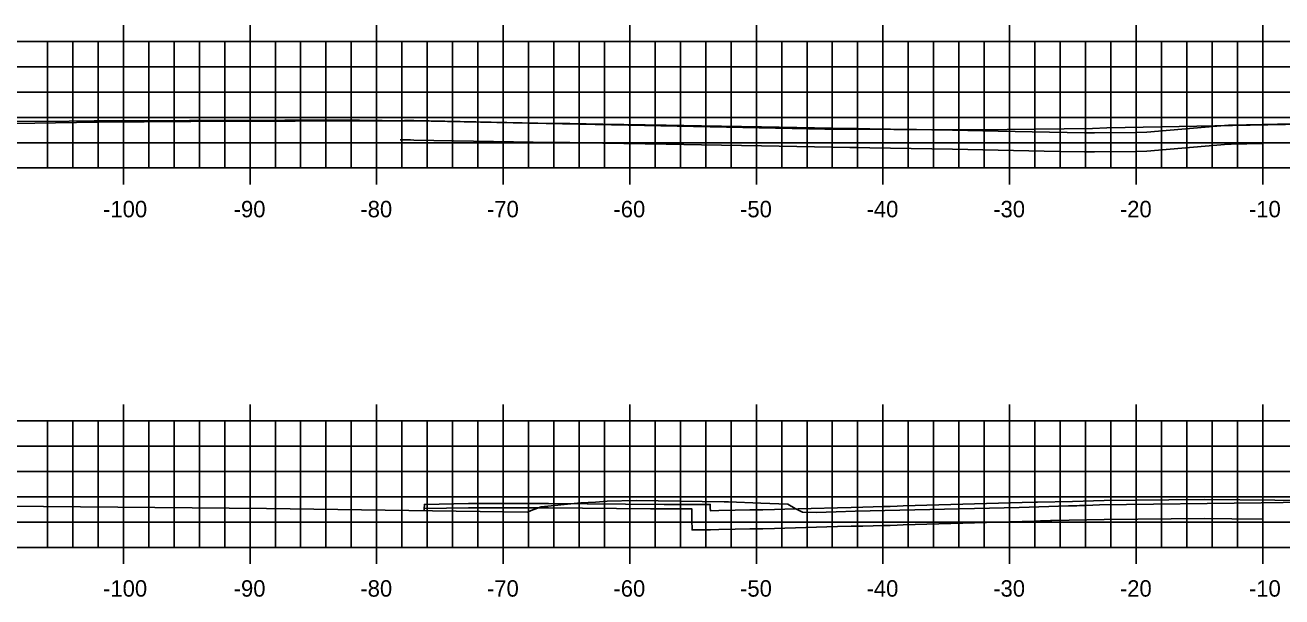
# Model space of a CAD drawing. Extents: x 40011 to 50684, y 49949 to 72236.
# Drawn here: x 41645.7 to 41745, y 68462.9 to 68508.1 of the extents above; entities that cross this region are included whole.
import ezdxf

# ---------------------------------------------------------------- set-up
doc = ezdxf.new("R2010")
doc.units = 0
for name, color, linetype in [('51', 7, 'Continuous'), ('53', 7, 'Continuous'), ('55', 7, 'Continuous'), ('57', 7, 'Continuous'), ('58', 7, 'Continuous'), ('59', 7, 'Continuous'), ('60', 7, 'Continuous')]:
    doc.layers.add(name, color=color, linetype=linetype)

msp = doc.modelspace()

# ---------------------------------------------------------------- linework, layer by layer
at = {"layer": '51'}
for p, q in [((41647.504, 68496.804), (41647.504, 68506.804)), ((41649.504, 68496.804), (41649.504, 68506.804)), ((41651.504, 68496.804), (41651.504, 68506.804)), ((41655.504, 68496.804), (41655.504, 68506.804)), ((41657.504, 68496.804), (41657.504, 68506.804)), ((41659.504, 68496.804), (41659.504, 68506.804)), ((41661.504, 68496.804), (41661.504, 68506.804)), ((41665.504, 68496.804), (41665.504, 68506.804)), ((41667.504, 68496.804), (41667.504, 68506.804)), ((41669.504, 68496.804), (41669.504, 68506.804)), ((41671.504, 68496.804), (41671.504, 68506.804)), ((41675.504, 68496.804), (41675.504, 68506.804)), ((41677.504, 68496.804), (41677.504, 68506.804)), ((41679.504, 68496.804), (41679.504, 68506.804)), ((41681.504, 68496.804), (41681.504, 68506.804)), ((41685.504, 68496.804), (41685.504, 68506.804)), ((41687.504, 68496.804), (41687.504, 68506.804)), ((41689.504, 68496.804), (41689.504, 68506.804)), ((41691.504, 68496.804), (41691.504, 68506.804)), ((41695.504, 68496.804), (41695.504, 68506.804)), ((41697.504, 68496.804), (41697.504, 68506.804)), ((41699.504, 68496.804), (41699.504, 68506.804)), ((41701.504, 68496.804), (41701.504, 68506.804)), ((41705.504, 68496.804), (41705.504, 68506.804)), ((41707.504, 68496.804), (41707.504, 68506.804)), ((41709.504, 68496.804), (41709.504, 68506.804)), ((41711.504, 68496.804), (41711.504, 68506.804)), ((41715.504, 68496.804), (41715.504, 68506.804)), ((41717.504, 68496.804), (41717.504, 68506.804)), ((41719.504, 68496.804), (41719.504, 68506.804)), ((41721.504, 68496.804), (41721.504, 68506.804)), ((41725.504, 68496.804), (41725.504, 68506.804)), ((41727.504, 68496.804), (41727.504, 68506.804)), ((41729.504, 68496.804), (41729.504, 68506.804)), ((41731.504, 68496.804), (41731.504, 68506.804)), ((41735.504, 68496.804), (41735.504, 68506.804)), ((41737.504, 68496.804), (41737.504, 68506.804)), ((41739.504, 68496.804), (41739.504, 68506.804)), ((41741.504, 68496.804), (41741.504, 68506.804)), ((41613.504, 68496.804), (41893.504, 68496.804)), ((41653.504, 68495.504), (41653.504, 68496.804)), ((41663.504, 68495.504), (41663.504, 68496.804)), ((41673.504, 68495.504), (41673.504, 68496.804)), ((41683.504, 68495.504), (41683.504, 68496.804)), ((41693.504, 68495.504), (41693.504, 68496.804)), ((41703.504, 68495.504), (41703.504, 68496.804)), ((41713.504, 68495.504), (41713.504, 68496.804)), ((41723.504, 68495.504), (41723.504, 68496.804)), ((41733.504, 68495.504), (41733.504, 68496.804)), ((41743.504, 68495.504), (41743.504, 68496.804)), ((41647.504, 68466.804), (41647.504, 68476.804)), ((41649.504, 68466.804), (41649.504, 68476.804)), ((41651.504, 68466.804), (41651.504, 68476.804)), ((41655.504, 68466.804), (41655.504, 68476.804)), ((41657.504, 68466.804), (41657.504, 68476.804)), ((41659.504, 68466.804), (41659.504, 68476.804)), ((41661.504, 68466.804), (41661.504, 68476.804)), ((41665.504, 68466.804), (41665.504, 68476.804)), ((41667.504, 68466.804), (41667.504, 68476.804)), ((41669.504, 68466.804), (41669.504, 68476.804)), ((41671.504, 68466.804), (41671.504, 68476.804)), ((41675.504, 68466.804), (41675.504, 68476.804)), ((41677.504, 68466.804), (41677.504, 68476.804)), ((41679.504, 68466.804), (41679.504, 68476.804)), ((41681.504, 68466.804), (41681.504, 68476.804)), ((41685.504, 68466.804), (41685.504, 68476.804)), ((41687.504, 68466.804), (41687.504, 68476.804)), ((41689.504, 68466.804), (41689.504, 68476.804)), ((41691.504, 68466.804), (41691.504, 68476.804)), ((41695.504, 68466.804), (41695.504, 68476.804)), ((41697.504, 68466.804), (41697.504, 68476.804)), ((41699.504, 68466.804), (41699.504, 68476.804)), ((41701.504, 68466.804), (41701.504, 68476.804)), ((41705.504, 68466.804), (41705.504, 68476.804)), ((41707.504, 68466.804), (41707.504, 68476.804)), ((41709.504, 68466.804), (41709.504, 68476.804)), ((41711.504, 68466.804), (41711.504, 68476.804)), ((41715.504, 68466.804), (41715.504, 68476.804)), ((41717.504, 68466.804), (41717.504, 68476.804)), ((41719.504, 68466.804), (41719.504, 68476.804)), ((41721.504, 68466.804), (41721.504, 68476.804)), ((41725.504, 68466.804), (41725.504, 68476.804)), ((41727.504, 68466.804), (41727.504, 68476.804)), ((41729.504, 68466.804), (41729.504, 68476.804)), ((41731.504, 68466.804), (41731.504, 68476.804)), ((41735.504, 68466.804), (41735.504, 68476.804)), ((41737.504, 68466.804), (41737.504, 68476.804)), ((41739.504, 68466.804), (41739.504, 68476.804)), ((41741.504, 68466.804), (41741.504, 68476.804)), ((41613.504, 68466.804), (41893.504, 68466.804)), ((41653.504, 68465.504), (41653.504, 68466.804)), ((41663.504, 68465.504), (41663.504, 68466.804)), ((41673.504, 68465.504), (41673.504, 68466.804)), ((41683.504, 68465.504), (41683.504, 68466.804)), ((41693.504, 68465.504), (41693.504, 68466.804)), ((41703.504, 68465.504), (41703.504, 68466.804)), ((41713.504, 68465.504), (41713.504, 68466.804)), ((41723.504, 68465.504), (41723.504, 68466.804)), ((41733.504, 68465.504), (41733.504, 68466.804)), ((41743.504, 68465.504), (41743.504, 68466.804))]:
    msp.add_line(p, q, dxfattribs=at)
at = {"layer": '53'}
for p, q in [((41613.504, 68504.804), (41893.504, 68504.804)), ((41613.504, 68502.804), (41893.504, 68502.804)), ((41613.504, 68500.804), (41893.504, 68500.804)), ((41613.504, 68498.804), (41893.504, 68498.804)), ((41613.504, 68474.804), (41893.504, 68474.804)), ((41613.504, 68472.804), (41893.504, 68472.804)), ((41613.504, 68470.804), (41893.504, 68470.804)), ((41613.504, 68468.804), (41893.504, 68468.804))]:
    msp.add_line(p, q, dxfattribs=at)
at = {"layer": '55'}
for p, q in [((41613.504, 68506.804), (41893.504, 68506.804)), ((41653.504, 68496.804), (41653.504, 68506.804)), ((41663.504, 68496.804), (41663.504, 68506.804)), ((41673.504, 68496.804), (41673.504, 68506.804)), ((41683.504, 68496.804), (41683.504, 68506.804)), ((41693.504, 68496.804), (41693.504, 68506.804)), ((41703.504, 68496.804), (41703.504, 68506.804)), ((41713.504, 68496.804), (41713.504, 68506.804)), ((41723.504, 68496.804), (41723.504, 68506.804)), ((41733.504, 68496.804), (41733.504, 68506.804)), ((41743.504, 68496.804), (41743.504, 68506.804)), ((41613.504, 68496.804), (41893.504, 68496.804)), ((41613.504, 68476.804), (41893.504, 68476.804)), ((41653.504, 68466.804), (41653.504, 68476.804)), ((41663.504, 68466.804), (41663.504, 68476.804)), ((41673.504, 68466.804), (41673.504, 68476.804)), ((41683.504, 68466.804), (41683.504, 68476.804)), ((41693.504, 68466.804), (41693.504, 68476.804)), ((41703.504, 68466.804), (41703.504, 68476.804)), ((41713.504, 68466.804), (41713.504, 68476.804)), ((41723.504, 68466.804), (41723.504, 68476.804)), ((41733.504, 68466.804), (41733.504, 68476.804)), ((41743.504, 68466.804), (41743.504, 68476.804)), ((41613.504, 68466.804), (41893.504, 68466.804))]:
    msp.add_line(p, q, dxfattribs=at)
at = {"layer": '57'}
for points in [[(41643.172, 68500.308), (41651.45, 68500.435), (41658.82, 68500.469), (41675.325, 68500.537), (41675.649, 68500.539), (41675.84, 68500.535), (41675.978, 68500.532), (41676.128, 68500.528), (41676.193, 68500.527), (41676.278, 68500.525), (41676.409, 68500.523), (41676.511, 68500.522), (41708.923, 68499.878), (41710.937, 68499.87), (41712.036, 68499.864), (41714.362, 68499.852), (41716.151, 68499.838), (41718.426, 68499.83), (41720.013, 68499.828), (41721.077, 68499.829), (41730.063, 68499.936), (41731.203, 68499.989), (41735.512, 68500.05), (41752.311, 68500.368)], [(41644.241, 68470.059), (41664.818, 68469.883), (41685.412, 68469.588), (41685.704, 68469.712), (41686.498, 68470.008), (41689.645, 68470.328), (41690.807, 68470.384), (41691.708, 68470.443), (41694.009, 68470.5), (41700.962, 68470.406), (41701.227, 68470.403), (41701.293, 68470.406), (41703.866, 68470.308), (41705.984, 68470.23), (41706.559, 68469.873), (41707.14, 68469.588), (41708.234, 68469.557), (41709.796, 68469.6), (41711.312, 68469.66), (41724.259, 68469.959), (41728.161, 68470.079), (41728.354, 68470.084), (41728.675, 68470.092), (41728.809, 68470.095), (41729.023, 68470.1), (41729.275, 68470.112), (41729.359, 68470.116), (41729.569, 68470.12), (41730.614, 68470.154), (41743.38, 68470.332), (41753.748, 68470.482)]]:
    msp.add_lwpolyline(points, dxfattribs=at)
at = {"layer": '58'}
for points in [[(41675.356, 68499.032), (41675.394, 68499.032), (41675.566, 68499.03), (41675.706, 68499.028), (41675.723, 68499.028), (41676.19, 68499.02), (41676.434, 68499.016), (41687.444, 68498.831), (41687.444, 68498.844), (41691.386, 68498.765), (41696.386, 68498.681), (41699.165, 68498.634), (41703.92, 68498.553), (41710.886, 68498.435), (41711.454, 68498.426), (41712.474, 68498.408), (41718.987, 68498.281), (41722.607, 68498.21), (41727.445, 68498.115), (41729.422, 68498.077), (41730.204, 68498.083), (41733.561, 68498.113), (41734.346, 68498.146), (41740.803, 68498.682), (41741.004, 68498.699), (41741.018, 68498.699), (41743.505, 68498.749)], [(41677.283, 68469.872), (41680.755, 68469.935), (41682.415, 68469.934), (41687.091, 68469.931), (41695.132, 68469.837), (41697.144, 68469.843), (41698.41, 68469.848), (41698.417, 68468.984), (41698.424, 68468.178), (41698.767, 68468.182), (41699.107, 68468.186), (41699.874, 68468.194), (41700.543, 68468.207), (41701.835, 68468.234), (41702.986, 68468.256), (41704.012, 68468.277), (41704.929, 68468.295), (41705.748, 68468.312), (41709.925, 68468.439), (41710.991, 68468.466), (41711.919, 68468.489), (41712.728, 68468.509), (41713.441, 68468.527), (41714.067, 68468.542), (41714.622, 68468.557), (41715.108, 68468.573), (41725.45, 68468.875), (41725.716, 68468.884), (41725.946, 68468.891), (41726.146, 68468.897), (41726.321, 68468.902), (41726.475, 68468.907), (41726.611, 68468.911), (41726.732, 68468.915), (41726.839, 68468.918), (41730.99, 68468.994), (41738.92, 68469.086), (41741.073, 68469.064), (41743.46, 68469.039), (41743.504, 68469.039)]]:
    msp.add_lwpolyline(points, dxfattribs=at)
at = {"layer": '59'}
for points in [[(41642.175, 68500.473), (41649.211, 68500.517), (41651.184, 68500.524), (41652.281, 68500.528), (41658.718, 68500.552), (41664.002, 68500.571), (41666.251, 68500.58), (41670.299, 68500.595), (41672.162, 68500.587), (41675.723, 68500.529), (41675.723, 68500.571), (41676.189, 68500.567), (41676.433, 68500.562), (41687.444, 68500.333), (41687.444, 68500.345), (41691.386, 68500.266), (41696.386, 68500.182), (41699.165, 68500.135), (41703.92, 68500.055), (41710.886, 68499.937), (41711.453, 68499.927), (41712.474, 68499.91), (41718.987, 68499.782), (41722.607, 68499.711), (41725.283, 68499.659), (41729.422, 68499.578), (41730.204, 68499.584), (41733.562, 68499.614), (41734.346, 68499.647), (41740.808, 68500.183), (41741.004, 68500.199), (41752.004, 68500.419)], [(41677.267, 68469.702), (41677.272, 68469.842), (41677.283, 68470.201), (41680.755, 68470.265), (41682.415, 68470.264), (41687.09, 68470.261), (41696.224, 68470.181), (41698.442, 68470.19), (41699.86, 68470.195), (41699.867, 68469.935), (41699.874, 68469.695), (41700.544, 68469.709), (41701.836, 68469.735), (41702.986, 68469.758), (41704.012, 68469.778), (41704.929, 68469.797), (41705.748, 68469.813), (41709.925, 68469.941), (41710.991, 68469.967), (41711.918, 68469.99), (41712.729, 68470.01), (41713.44, 68470.028), (41714.067, 68470.044), (41714.622, 68470.058), (41715.108, 68470.074), (41725.45, 68470.377), (41725.715, 68470.385), (41728.487, 68470.419), (41730.99, 68470.496), (41736.087, 68470.554), (41738.921, 68470.587), (41750.004, 68470.475)]]:
    msp.add_lwpolyline(points, dxfattribs=at)
at = {"layer": '60'}
for p, q in [((41653.504, 68508.104), (41653.504, 68506.804)), ((41663.504, 68508.104), (41663.504, 68506.804)), ((41673.504, 68508.104), (41673.504, 68506.804)), ((41683.504, 68508.104), (41683.504, 68506.804)), ((41693.504, 68508.104), (41693.504, 68506.804)), ((41703.504, 68508.104), (41703.504, 68506.804)), ((41713.504, 68508.104), (41713.504, 68506.804)), ((41723.504, 68508.104), (41723.504, 68506.804)), ((41733.504, 68508.104), (41733.504, 68506.804)), ((41743.504, 68508.104), (41743.504, 68506.804)), ((41653.504, 68478.104), (41653.504, 68476.804)), ((41663.504, 68478.104), (41663.504, 68476.804)), ((41673.504, 68478.104), (41673.504, 68476.804)), ((41683.504, 68478.104), (41683.504, 68476.804)), ((41693.504, 68478.104), (41693.504, 68476.804)), ((41703.504, 68478.104), (41703.504, 68476.804)), ((41713.504, 68478.104), (41713.504, 68476.804)), ((41723.504, 68478.104), (41723.504, 68476.804)), ((41733.504, 68478.104), (41733.504, 68476.804)), ((41743.504, 68478.104), (41743.504, 68476.804))]:
    msp.add_line(p, q, dxfattribs=at)

# ---------------------------------------------------------------- texts
at = {"layer": '51'}
for s, p in [('-100', (41651.897, 68492.904)), ('-90', (41662.213, 68492.904)), ('-80', (41672.22, 68492.904)), ('-70', (41682.222, 68492.904)), ('-60', (41692.213, 68492.904)), ('-50', (41702.216, 68492.904)), ('-40', (41712.207, 68492.904)), ('-30', (41722.215, 68492.904)), ('-20', (41732.222, 68492.904)), ('-10', (41742.419, 68492.904)), ('-100', (41651.897, 68462.904)), ('-90', (41662.213, 68462.904)), ('-80', (41672.22, 68462.904)), ('-70', (41682.222, 68462.904)), ('-60', (41692.213, 68462.904)), ('-50', (41702.216, 68462.904)), ('-40', (41712.207, 68462.904)), ('-30', (41722.215, 68462.904)), ('-20', (41732.222, 68462.904)), ('-10', (41742.419, 68462.904))]:
    msp.add_text(s, height=1.3, dxfattribs=at).set_placement(p)

doc.saveas('drawing.dxf')
